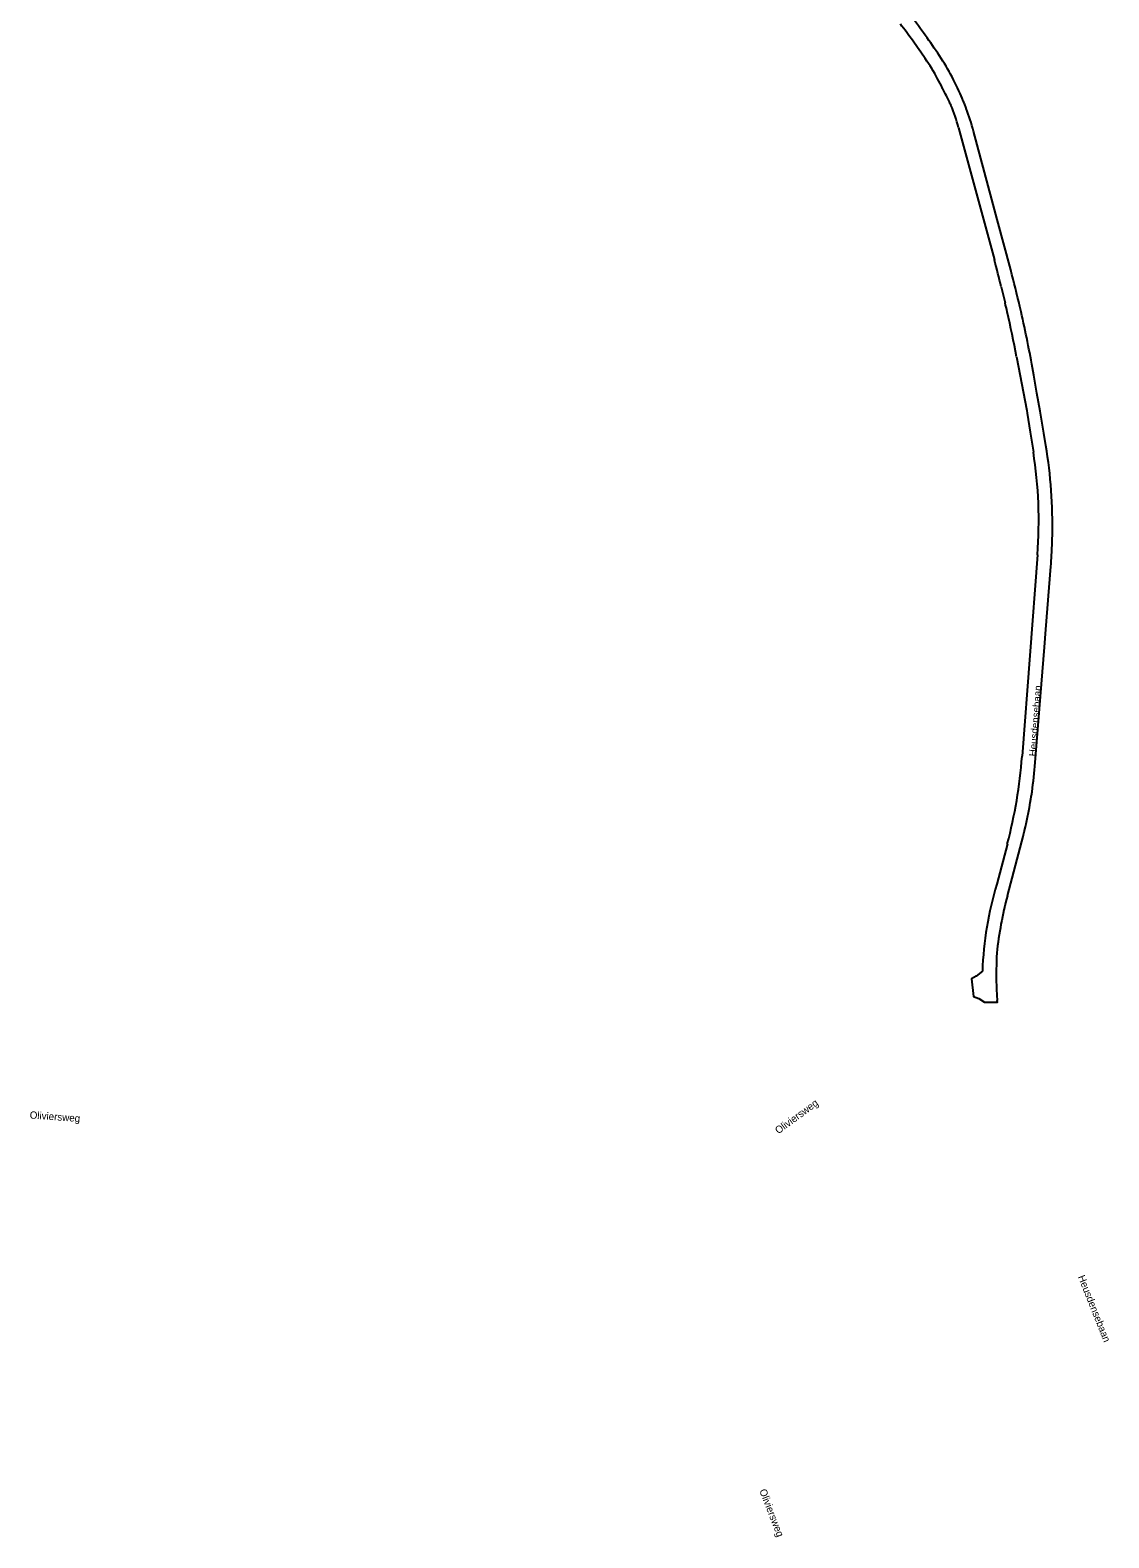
# Model space of a CAD drawing. Extents: x 141000 to 143000, y 400580 to 403500.
# Drawn here: x 141094 to 141463, y 400580 to 401096 of the extents above; entities that cross this region are included whole.
import ezdxf

# ---------------------------------------------------------------- set-up
doc = ezdxf.new("R2010")
doc.units = 0
doc.layers.add('gg-anno-openbare ruimte label', color=7, linetype='Continuous')
doc.layers.add('gx-grn-maaiveld', color=7, linetype='Continuous')

msp = doc.modelspace()

# ---------------------------------------------------------------- linework, layer by layer
at = {"layer": 'gx-grn-maaiveld'}
for p, q in [((141411.53, 401063.05), (141423.77, 401017.77)), ((141438.51, 400916.87), (141433.27, 400847.87)), ((141428.23, 400800.13), (141433.19, 400818.72)), ((141428.21, 400817.87), (141424.57, 400804.11))]:
    msp.add_line(p, q, dxfattribs=at)
for points in [[(141398.86, 401096.44), (141398.49, 401096.95), (141398.27, 401097.24), (141397.82, 401097.87), (141397.45, 401098.37), (141397.08, 401098.88), (141396.78, 401099.29), (141396.41, 401099.79), (141396.03, 401100.31), (141395.73, 401100.71), (141395.36, 401101.21), (141394.02, 401103), (141387.69, 401110.99), (141377.25, 401124.17), (141371.17, 401132.07), (141365.37, 401140.03)], [(141414.17, 401069.62), (141414.12, 401069.76), (141414.01, 401070.06), (141413.85, 401070.47), (141413.8, 401070.61), (141413.53, 401071.31), (141413.48, 401071.45), (141413.2, 401072.16), (141413.15, 401072.29), (141412.78, 401073.17), (141412.43, 401073.96), (141412.08, 401074.75)], [(141408.7, 401071.27), (141408.81, 401071.02), (141408.91, 401070.77)], [(141429.35, 401014.36), (141424.73, 401031.65), (141422.92, 401038.45), (141416.67, 401061.85)], [(141426.14, 401008.6), (141426.59, 401006.78), (141427.03, 401004.96), (141427.46, 401003.14)], [(141433.2, 400998.73), (141432.91, 401000), (141432.48, 401001.85)], [(141431.39, 400984.61), (141434.87, 400966.29), (141435.03, 400965.28), (141436.05, 400958.79), (141437.11, 400951.98)], [(141441.42, 400954.25), (141440.69, 400958.49), (141439.4, 400965.99), (141438.32, 400972.2), (141437.27, 400978.29)], [(141437.61, 400844.41), (141440.88, 400885.18), (141441.37, 400891.29), (141443.09, 400912.78)], [(141436.07, 400832.01), (141436.13, 400832.36), (141436.19, 400832.73), (141436.25, 400833.08), (141436.3, 400833.42), (141436.38, 400833.9), (141436.41, 400834.14), (141436.47, 400834.49)], [(141419.67, 400774.32), (141417.59, 400772.62), (141415.98, 400771.7), (141416.66, 400765.62), (141418.41, 400764.96), (141420.36, 400763.68), (141424.79, 400763.72), (141424.76, 400763.98), (141424.72, 400764.24)]]:
    msp.add_lwpolyline(points, dxfattribs=at)
for centre, radius, start, end in [((141116.29, 400892.3), 344.03, 34.4068, 36.8425), ((141093.66, 400876.31), 376.3, 34.4896, 35.8026), ((141326.17, 401035.94), 94.27, 24.3108, 34.545), ((141354.36, 401054.18), 56.14, 27.1758, 35.3986), ((141270.42, 401005.89), 152.94, 27.5042, 28.9041), ((141267.03, 401003.87), 156.89, 25.4442, 27.5899), ((141358, 401049.21), 55.29, 14.4906, 22.9481), ((141317.42, 401034.19), 103.03, 15.5727, 20.1114), ((140986.24, 400899.58), 453.21, 13.9189, 15.1162), ((141028.36, 400907.34), 415.03, 13.1623, 14.9425), ((141009.3, 400905.01), 429.51, 12.7752, 13.206), ((140991.69, 400901.01), 447.58, 10.7656, 12.7769), ((141030.29, 400907.8), 413.04, 9.8258, 12.7175), ((141270.48, 400926.61), 173.16, 358.918, 9.1863), ((141286.56, 400928.41), 152.39, 355.6575, 8.8992), ((141271.74, 400926.55), 171.9, 356.7528, 358.9297), ((141273.66, 400926.41), 169.97, 355.4021, 356.7641), ((141267.04, 400860.49), 166.7, 345.1878, 355.6571), ((141293.06, 400856.04), 145.02, 351.4556, 355.4028), ((141293.49, 400855.97), 144.58, 345.067, 350.4593), ((141541.7, 400769.56), 122.12, 163.5612, 177.7643), ((141553.58, 400766.78), 129.71, 165.0998, 173.912), ((141569.31, 400773.44), 144.89, 177.1934, 181.6183), ((141572.61, 400773.64), 148.19, 181.6596, 183.6352)]:
    msp.add_arc(centre, radius, start, end, dxfattribs=at)

# ---------------------------------------------------------------- texts
at = {"layer": 'gg-anno-openbare ruimte label'}
for s, rotation, p in [('Heusdensebaan', 85.6, (141438.08, 400847.76)), ('Oliviersweg', 355.9, (141093.6, 400723.88)), ('Oliviersweg', 36.3, (141349.85, 400718.43)), ('Heusdensebaan', 291.7, (141452.3, 400669.66)), ('Oliviersweg', 291.2, (141343.29, 400596.48))]:
    msp.add_text(s, height=2.5, rotation=rotation, dxfattribs=at).set_placement(p)

doc.saveas('drawing.dxf')
